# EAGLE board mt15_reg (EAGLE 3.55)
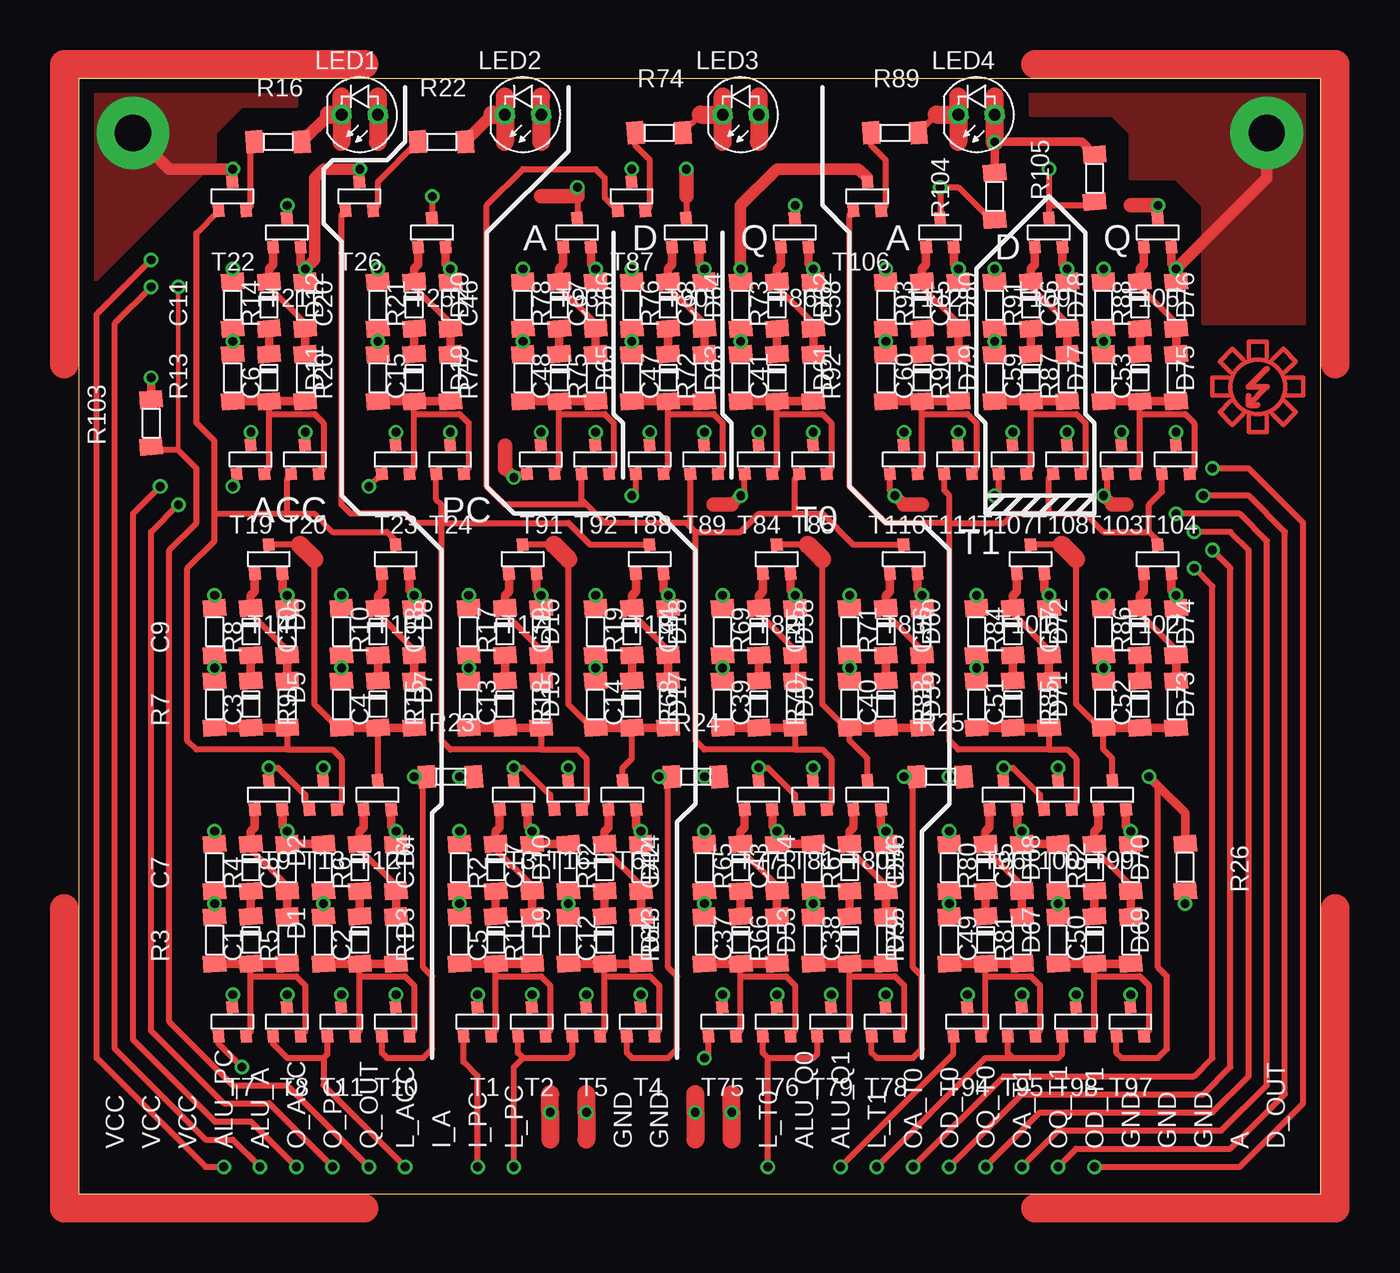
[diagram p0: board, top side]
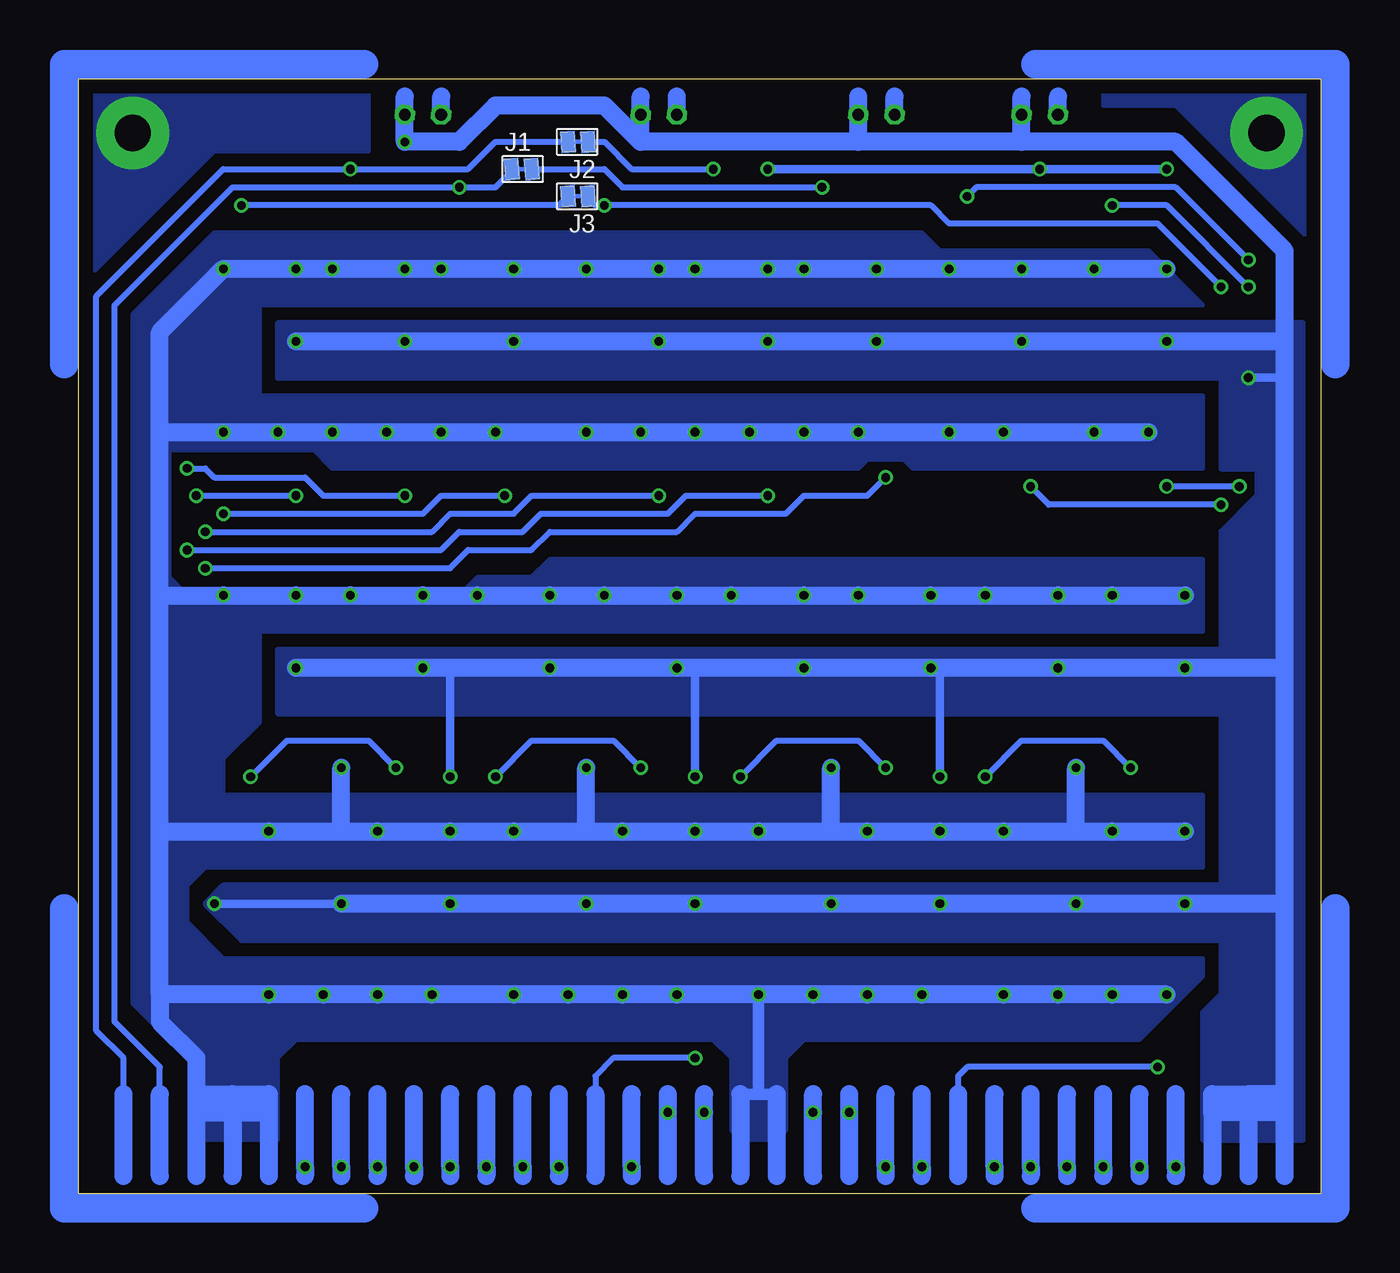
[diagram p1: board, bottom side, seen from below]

Size 86.97 x 78.09 mm. Coordinates in mm from the lower left corner, seen from the top.
Outline: 0,0 86.97,0 86.97,78.09 0,78.09 0,0
Copper layers used: Top, Bottom

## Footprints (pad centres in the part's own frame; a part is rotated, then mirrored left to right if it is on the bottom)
04 = smd 1.194 x 1.6 rotated 4.4:  1.651,0 | smd 1.194 x 1.6 rotated 4.3:  -1.651,0
04D = smd 1.194 x 1.6 rotated 4.3:  1.651,0 | smd 1.194 x 1.6 rotated 4.4:  -1.651,0
MPII = smd 1.016 x 1.524 rotated 4.3:  -0.762,0 | smd 1.016 x 1.524 rotated 4.4:  0.635,0
D-5S = drill 0.813 pad 1.397 octagon:  -1.27,0;  1.27,0
T-23 = smd 0.787 x 0.889 rotated 4.4:  0.991,1.016 | smd 0.787 x 0.889 rotated 4.3:  -0.94,1.016 | smd 0.787 x 0.889 rotated 4.5:  0.025,-1.016

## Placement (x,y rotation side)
C1  1n  [04]  14.61,17.78 90 top
C2  1n  [04]  22.23,17.78 90 top
C3  1n  [04]  14.61,34.29 90 top
C4  1n  [04]  23.5,34.29 90 top
C5  1n  [04]  31.75,17.78 90 top
C6  1n  [04]  15.88,57.15 90 top
C7  100n  [04]  9.53,22.86 90 top
C8  100n  [04]  17.14,22.86 90 top
C9  100n  [04]  9.53,39.37 90 top
C10  100n  [04]  18.41,39.37 90 top
C11  100n  [04]  10.79,62.23 90 top
C12  1n  [04]  39.37,17.78 90 top
C13  1n  [04]  32.38,34.29 90 top
C14  1n  [04]  41.27,34.29 90 top
C15  1n  [04]  26.04,57.15 90 top
C16  100n  [04]  26.67,22.86 90 top
C17  100n  [04]  34.29,22.86 90 top
C18  100n  [04]  27.3,39.37 90 top
C19  100n  [04]  36.2,39.37 90 top
C20  100n  [04]  20.95,62.23 90 top
C37  1n  [04]  48.9,17.78 90 top
C38  1n  [04]  56.52,17.78 90 top
C39  1n  [04]  50.16,34.29 90 top
C40  1n  [04]  59.05,34.29 90 top
C41  1n  [04]  51.44,57.15 90 top
C42  100n  [04]  43.81,22.86 90 top
C43  100n  [04]  51.44,22.86 90 top
C44  100n  [04]  45.09,39.37 90 top
C45  100n  [04]  53.98,39.37 90 top
C46  100n  [04]  31.11,62.23 90 top
C47  1n  [04]  43.81,57.15 90 top
C48  1n  [04]  36.2,57.15 90 top
C49  1n  [04]  66.04,17.78 90 top
C50  1n  [04]  73.66,17.78 90 top
C51  1n  [04]  67.94,34.29 90 top
C52  1n  [04]  76.83,34.29 90 top
C53  1n  [04]  76.83,57.15 90 top
C54  100n  [04]  60.96,22.86 90 top
C55  100n  [04]  68.58,22.86 90 top
C56  100n  [04]  62.87,39.37 90 top
C57  100n  [04]  71.75,39.37 90 top
C58  100n  [04]  56.52,62.23 90 top
C59  1n  [04]  69.22,57.15 90 top
C60  1n  [04]  61.59,57.15 90 top
C65  100n  [04]  64.14,62.23 90 top
C66  100n  [04]  71.75,62.23 90 top
C67  100n  [04]  38.73,62.23 90 top
C68  100n  [04]  46.35,62.23 90 top
D1  1N4148  [04D]  12.06,17.78 270 top
D2  1N4148  [04D]  12.06,22.86 270 top
D3  1N4148  [04D]  19.68,17.78 270 top
D4  1N4148  [04D]  19.68,22.86 270 top
D5  1N4148  [04D]  12.06,34.29 270 top
D6  1N4148  [04D]  12.06,39.37 270 top
D7  1N4148  [04D]  20.95,34.29 270 top
D8  1N4148  [04D]  20.95,39.37 270 top
D9  1N4148  [04D]  29.21,17.78 270 top
D10  1N4148  [04D]  29.21,22.86 270 top
D11  1N4148  [04D]  13.34,57.15 270 top
D12  1N4148  [04D]  13.34,62.23 270 top
D13  1N4148  [04D]  36.83,17.78 270 top
D14  1N4148  [04D]  36.83,22.86 270 top
D15  1N4148  [04D]  29.84,34.29 270 top
D16  1N4148  [04D]  29.84,39.37 270 top
D17  1N4148  [04D]  38.73,34.29 270 top
D18  1N4148  [04D]  38.73,39.37 270 top
D19  1N4148  [04D]  23.5,57.15 270 top
D20  1N4148  [04D]  23.5,62.23 270 top
D53  1N4148  [04D]  46.35,17.78 270 top
D54  1N4148  [04D]  46.35,22.86 270 top
D55  1N4148  [04D]  53.98,17.78 270 top
D56  1N4148  [04D]  53.98,22.86 270 top
D57  1N4148  [04D]  47.62,34.29 270 top
D58  1N4148  [04D]  47.62,39.37 270 top
D59  1N4148  [04D]  56.52,34.29 270 top
D60  1N4148  [04D]  56.52,39.37 270 top
D61  1N4148  [04D]  48.9,57.15 270 top
D62  1N4148  [04D]  48.9,62.23 270 top
D63  1N4148  [04D]  41.27,57.15 270 top
D64  1N4148  [04D]  41.27,62.23 270 top
D65  1N4148  [04D]  33.66,57.15 270 top
D66  1N4148  [04D]  33.66,62.23 270 top
D67  1N4148  [04D]  63.5,17.78 270 top
D68  1N4148  [04D]  63.5,22.86 270 top
D69  1N4148  [04D]  71.12,17.78 270 top
D70  1N4148  [04D]  71.12,22.86 270 top
D71  1N4148  [04D]  65.41,34.29 270 top
D72  1N4148  [04D]  65.41,39.37 270 top
D73  1N4148  [04D]  74.3,34.29 270 top
D74  1N4148  [04D]  74.3,39.37 270 top
D75  1N4148  [04D]  74.3,57.15 270 top
D76  1N4148  [04D]  74.3,62.23 270 top
D77  1N4148  [04D]  66.67,57.15 270 top
D78  1N4148  [04D]  66.67,62.23 270 top
D79  1N4148  [04D]  59.05,57.15 270 top
D80  1N4148  [04D]  59.05,62.23 270 top
J1  JUMPII  [MPII]  55.88,71.75 0 bottom
J2  JUMPII  [MPII]  52.07,73.66 180 bottom
J3  JUMPII  [MPII]  52.07,69.85 180 bottom
LED1  LED-5S  [D-5S]  19.68,75.56 180 top
LED2  LED-5S  [D-5S]  31.11,75.56 180 top
LED3  LED-5S  [D-5S]  46.35,75.56 180 top
LED4  LED-5S  [D-5S]  62.87,75.56 180 top
R1  390  [04]  26.67,17.78 90 top
R2  820  [04]  31.75,22.86 90 top
R3  390  [04]  9.53,17.78 90 top
R4  820  [04]  14.61,22.86 90 top
R5  390  [04]  17.14,17.78 90 top
R6  820  [04]  22.23,22.86 90 top
R7  390  [04]  9.53,34.29 90 top
R8  820  [04]  14.61,39.37 90 top
R9  390  [04]  18.41,34.29 90 top
R10  820  [04]  23.5,39.37 90 top
R11  390  [04]  34.29,17.78 90 top
R12  820  [04]  39.37,22.86 90 top
R13  390  [04]  10.79,57.15 90 top
R14  820  [04]  15.88,62.23 90 top
R15  390  [04]  27.3,34.29 90 top
R16  27  [04]  13.97,73.66 0 top
R17  820  [04]  32.38,39.37 90 top
R18  390  [04]  36.2,34.29 90 top
R19  820  [04]  41.27,39.37 90 top
R20  390  [04]  20.95,57.15 90 top
R21  820  [04]  26.04,62.23 90 top
R22  27  [04]  25.4,73.66 0 top
R23  330  [04]  26.04,29.21 0 top
R24  330  [04]  43.18,29.21 0 top
R25  330  [04]  60.33,29.21 0 top
R26  330  [04]  77.47,22.86 270 top
R64  390  [04]  43.81,17.78 90 top
R65  820  [04]  48.9,22.86 90 top
R66  390  [04]  51.44,17.78 90 top
R67  820  [04]  56.52,22.86 90 top
R68  390  [04]  45.09,34.29 90 top
R69  820  [04]  50.16,39.37 90 top
R70  390  [04]  53.98,34.29 90 top
R71  820  [04]  59.05,39.37 90 top
R72  390  [04]  46.35,57.15 90 top
R73  820  [04]  51.44,62.23 90 top
R74  27  [04]  40.64,74.3 0 top
R75  390  [04]  38.73,57.15 90 top
R76  820  [04]  43.81,62.23 90 top
R77  390  [04]  31.11,57.15 90 top
R78  820  [04]  36.2,62.23 90 top
R79  390  [04]  60.96,17.78 90 top
R80  820  [04]  66.04,22.86 90 top
R81  390  [04]  68.58,17.78 90 top
R82  820  [04]  73.66,22.86 90 top
R83  390  [04]  62.87,34.29 90 top
R84  820  [04]  67.94,39.37 90 top
R85  390  [04]  71.75,34.29 90 top
R86  820  [04]  76.83,39.37 90 top
R87  390  [04]  71.75,57.15 90 top
R88  820  [04]  76.83,62.23 90 top
R89  27  [04]  57.15,74.3 0 top
R90  390  [04]  64.14,57.15 90 top
R91  820  [04]  69.22,62.23 90 top
R92  390  [04]  56.52,57.15 90 top
R93  820  [04]  61.59,62.23 90 top
R103  330  [04]  5.08,53.98 90 top
R104  330  [04]  64.14,69.85 90 top
R105  330  [04]  71.12,71.12 90 top
T1  BC857  [T-23]  27.94,12.06 180 top
T2  BC857  [T-23]  31.75,12.06 180 top
T3  BC847  [T-23]  30.48,27.94 180 top
T4  BC857  [T-23]  39.37,12.06 180 top
T5  BC857  [T-23]  35.56,12.06 180 top
T6  BC847  [T-23]  38.1,27.94 180 top
T7  BC857  [T-23]  10.79,12.06 180 top
T8  BC857  [T-23]  14.61,12.06 180 top
T9  BC847  [T-23]  13.34,27.94 180 top
T10  BC857  [T-23]  22.23,12.06 180 top
T11  BC857  [T-23]  18.41,12.06 180 top
T12  BC847  [T-23]  20.95,27.94 180 top
T13  BC857  [T-23]  17.14,27.94 180 top
T14  BC847  [T-23]  13.34,44.45 180 top
T15  BC847  [T-23]  22.23,44.45 180 top
T16  BC857  [T-23]  34.29,27.94 180 top
T17  BC847  [T-23]  31.11,44.45 180 top
T18  BC847  [T-23]  40.01,44.45 180 top
T19  BC857  [T-23]  12.06,51.44 180 top
T20  BC857  [T-23]  15.88,51.44 180 top
T21  BC847  [T-23]  14.61,67.31 180 top
T22  BC857  [T-23]  10.79,69.85 180 top
T23  BC857  [T-23]  22.23,51.44 180 top
T24  BC857  [T-23]  26.04,51.44 180 top
T25  BC847  [T-23]  24.77,67.31 180 top
T26  BC857  [T-23]  19.68,69.85 180 top
T75  BC857  [T-23]  45.09,12.06 180 top
T76  BC857  [T-23]  48.9,12.06 180 top
T77  BC847  [T-23]  47.62,27.94 180 top
T78  BC857  [T-23]  56.52,12.06 180 top
T79  BC857  [T-23]  52.7,12.06 180 top
T80  BC847  [T-23]  55.24,27.94 180 top
T81  BC857  [T-23]  51.44,27.94 180 top
T82  BC847  [T-23]  48.9,44.45 180 top
T83  BC847  [T-23]  57.78,44.45 180 top
T84  BC857  [T-23]  47.62,51.44 180 top
T85  BC857  [T-23]  51.44,51.44 180 top
T86  BC847  [T-23]  50.16,67.31 180 top
T87  BC857  [T-23]  38.73,69.85 180 top
T88  BC857  [T-23]  40.01,51.44 180 top
T89  BC857  [T-23]  43.81,51.44 180 top
T90  BC847  [T-23]  42.55,67.31 180 top
T91  BC857  [T-23]  32.38,51.44 180 top
T92  BC857  [T-23]  36.2,51.44 180 top
T93  BC847  [T-23]  34.92,67.31 180 top
T94  BC857  [T-23]  62.23,12.06 180 top
T95  BC857  [T-23]  66.04,12.06 180 top
T96  BC847  [T-23]  64.77,27.94 180 top
T97  BC857  [T-23]  73.66,12.06 180 top
T98  BC857  [T-23]  69.85,12.06 180 top
T99  BC847  [T-23]  72.39,27.94 180 top
T100  BC857  [T-23]  68.58,27.94 180 top
T101  BC847  [T-23]  66.67,44.45 180 top
T102  BC847  [T-23]  75.56,44.45 180 top
T103  BC857  [T-23]  73.03,51.44 180 top
T104  BC857  [T-23]  76.83,51.44 180 top
T105  BC847  [T-23]  75.56,67.31 180 top
T106  BC857  [T-23]  55.24,69.85 180 top
T107  BC857  [T-23]  65.41,51.44 180 top
T108  BC857  [T-23]  69.22,51.44 180 top
T109  BC847  [T-23]  67.94,67.31 180 top
T110  BC857  [T-23]  57.78,51.44 180 top
T111  BC857  [T-23]  61.59,51.44 180 top
T112  BC847  [T-23]  60.33,67.31 180 top
U$46  []  82.55,56.52 0 top

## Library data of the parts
C1-C20 C37-C60 C65-C68 D1-D20 D53-D80 R1-R26 R64-R93 R103-R105 = DISCRETE
J1-J3 = jg
LED1-LED4 = M68XXX
T1 T2 T4 T5 T7 T8 T10 T11 T13 T16 T19 T20 T22-T24 T26 T75 T76 T78 T79 T81 T84 T85 T87-T89 T91 T92 T94 T95 T97 T98 T100 T103 T104 T106-T108 T110 T111 = PNP
T3 T6 T9 T12 T14 T15 T17 T18 T21 T25 T77 T80 T82 T83 T86 T90 T93 T96 T99 T101 T102 T105 T109 T112 = NPN
U$46 = TAF

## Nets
A: J1. R104. T93. T112.
ALU_A: T21.
ALU_PC: T25.
ALU_Q0: T75.
ALU_Q1: T94.
D_OUT: J2. R105. T90. T109.
GND: C7. C8. C9. C10. C11. C16. C17. C18. C19. C20. C42. C43. C44. C45. C46. C54. C55. C56. C57. C58. C65. C66. C67. C68. R2. R4. R6. R8. R10. R12. R14. R17. R19. R21. R65. R67. R69. R71. R73. R76. R78. R80. R82. R84. R86. R88. R91. R93. T1. T2. T3. T4. T5. T6. T7. T8. T9. T10. T11. T12. T13. T14. T15. T16. T17. T18. T19. T20. T21. T22. T23. T24. T25. T26. T75. T76. T77. T78. T79. T80. T81. T82. T83. T84. T85. T86. T87. T88. T89. T90. T91. T92. T93. T94. T95. T96. T97. T98. T99. T100. T101. T102. T103. T104. T105. T106. T107. T108. T109. T110. T111. T112.
I_A: T7.
I_PC: T1.
L_ACC: T8. T11.
L_PC: T2. T5.
L_T0: T76. T79.
L_T1: T95. T98.
N$9: C5. D9. R1. T1. T2.
N$10: D9. D10.
N$11: C1. D1. R3. T7. T8.
N$12: D1. D2.
N$13: C5. D10. R2. T3.
N$14: C1. D2. R4. T9.
N$15: D5. D6.
N$17: C2. D3. R5. T10. T11.
N$18: D3. D4.
N$19: C2. D4. R6. T12.
N$20: C3. D6. R8. T14.
N$21: D7. D8.
N$22: C4. D8. R10. T15.
N$23: C4. D7. R9. T12. T14.
N$24: C3. D5. R7. T13. T15. T20. T22.
N$25: R16. T22.
N$26: R24. T3. T4. T16.
N$27: C12. D13. R11. T4. T5.
N$28: D13. D14.
N$29: LED1. R16.
N$30: C6. D11. R13. T19. T20.
N$31: D11. D12.
N$32: C6. D12. R14. T21.
N$33: C12. D14. R12. T6.
N$34: D15. D16.
N$35: C13. D16. R17. T17.
N$36: D17. D18.
N$37: C14. D18. R19. T18.
N$38: C14. D17. R18. T6. T17.
N$39: C13. D15. R15. T16. T18. T24. T26.
N$40: C15. D19. R20. T23. T24.
N$41: D19. D20.
N$42: C15. D20. R21. T25.
N$43: R22. T26.
N$44: LED2. R22.
N$45: R23. T9. T10. T13.
N$93: C37. D53. R64. T75. T76.
N$94: D53. D54.
N$95: C37. D54. R65. T77.
N$96: R25. T77. T78. T81.
N$97: C38. D55. R66. T78. T79.
N$98: D55. D56.
N$99: C38. D56. R67. T80.
N$100: D57. D58.
N$101: C39. D58. R69. T82.
N$102: D59. D60.
N$103: C40. D60. R71. T83.
N$104: C40. D59. R70. T80. T82.
N$105: C39. D57. R68. T81. T83. T85. T87. T89. T92.
N$106: C41. D61. R72. T84. T85.
N$107: D61. D62.
N$108: C41. D62. R73. T86.
N$109: R74. T87.
N$110: LED3. R74.
N$111: C49. D67. R79. T94. T95.
N$112: C47. D63. R75. T88. T89.
N$113: D63. D64.
N$114: C47. D64. R76. T90.
N$115: D67. D68.
N$116: C48. D65. R77. T91. T92.
N$117: D65. D66.
N$118: C48. D66. R78. T93.
N$119: C49. D68. R80. T96.
N$120: R26. T96. T97. T100.
N$121: C50. D69. R81. T97. T98.
N$122: D69. D70.
N$123: C50. D70. R82. T99.
N$124: D71. D72.
N$125: C51. D72. R84. T101.
N$126: D73. D74.
N$127: C52. D74. R86. T102.
N$128: C52. D73. R85. T99. T101.
N$129: C51. D71. R83. T100. T102. T104. T106. T108. T111.
N$130: C53. D75. R87. T103. T104.
N$131: D75. D76.
N$132: C53. D76. R88. T105.
N$133: R89. T106.
N$134: LED4. R89.
N$135: C59. D77. R90. T107. T108.
N$136: D77. D78.
N$137: C59. D78. R91. T109.
N$138: C60. D79. R92. T110. T111.
N$139: D79. D80.
N$140: C60. D80. R93. T112.
O_ACC: T19.
O_PC: T23.
OA_T0: T91.
OA_T1: T110.
OD_T0: T88.
OD_T1: T107.
OQ_T0: T84.
OQ_T1: T103.
Q_OUT: J3. R103. T86. T105.
VCC: C7. C8. C9. C10. C11. C16. C17. C18. C19. C20. C42. C43. C44. C45. C46. C54. C55. C56. C57. C58. C65. C66. C67. C68. LED1. LED2. LED3. LED4. R1. R3. R5. R7. R9. R11. R13. R15. R18. R20. R23. R24. R25. R26. R64. R66. R68. R70. R72. R75. R77. R79. R81. R83. R85. R87. R90. R92. R103. R104. R105.

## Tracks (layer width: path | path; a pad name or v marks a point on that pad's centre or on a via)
A  (via drill 0.61 pad 1.02)
  Top 0.406: T93. 34.92,68.35 34.92,69.85 | T112. 60.33,68.35 v60.33,70.48 61.59,70.48 63.88,68.2 R104.
  Top 1.016: v34.92,70.48 34.92,69.85 32.38,69.85
  Bottom 0.305: 56.64,71.75 J1.
  Bottom 0.406: 81.28,6.99 81.28,8.89 84.45,12.06 84.45,62.23 76.2,70.48 v60.33,70.48 57.78,70.48 56.64,71.63 56.64,71.75 | J1. 50.16,71.75 48.9,70.48 v34.92,70.48
  Bottom 1.27: 81.28,1.27 81.28,6.99
ALU_A  (via drill 0.61 pad 1.02)
  Top 0.406: T21. 14.61,68.35 v14.61,69.22 | v5.08,63.5 2.54,60.96 2.54,10.16 8.89,3.81 10.79,3.81 v12.7,1.91
  Bottom 0.406: v14.61,69.22 10.79,69.22 v5.08,63.5
  Bottom 1.27: 12.7,1.27 v12.7,1.91 12.7,6.99
ALU_PC  (via drill 0.61 pad 1.02)
  Top 0.406: T25. 24.77,68.35 v24.77,69.85 | v5.08,65.41 1.27,61.59 1.27,9.53 8.89,1.91 v10.16,1.91
  Bottom 0.406: v5.08,65.41 10.16,70.48 24.13,70.48 v24.77,69.85
  Bottom 1.27: 10.16,1.27 v10.16,1.91 10.16,6.99
ALU_Q0  (via drill 0.61 pad 1.02)
  Top 0.406: 44.09,11.05 44.09,9.8 v43.81,9.53
  Bottom 0.406: 50.8,6.99 50.8,8.26 49.53,9.53 v43.81,9.53
  Bottom 1.27: 50.8,6.99 50.8,1.27
ALU_Q1  (via drill 0.61 pad 1.02)
  Top 0.406: 61.24,11.05 61.24,9.8 v53.34,1.91
  Bottom 1.27: 53.34,1.27 v53.34,1.91 53.34,6.99
D_OUT  (via drill 0.61 pad 1.02)
  Top 0.406: T90. 42.55,68.35 42.55,69.85 | T109. 67.94,68.35 67.94,69.22 | v67.94,71.75 67.94,69.22 | R105. 70.87,69.22 67.94,69.22
  Top 1.016: v42.55,71.75 42.55,69.85
  Bottom 0.305: J2. 51.31,73.66
  Bottom 0.406: 83.82,6.99 83.82,9.53 85.72,11.43 85.72,62.87 76.83,71.75 v67.94,71.75 59.69,71.75 57.78,73.66 J2. | 51.31,73.66 50.16,73.66 48.26,71.75 v42.55,71.75
  Bottom 1.27: 83.82,1.27 83.82,6.99
GND  (via drill 0.61 pad 1.02, 2.54 pad 5.08)
  Top 0.406: T22. 10.79,70.89 v10.79,71.75 | T26. 19.68,70.89 v19.68,71.75 | T87. 38.73,70.89 v38.73,71.75
  Top 0.61: T7. 10.79,13.11 v10.79,13.97 | T8. 14.61,13.11 v14.61,13.97 | T1. 27.94,13.11 v27.94,13.97 | T2. 31.75,13.11 v31.75,13.97 | T75. 45.09,13.11 v45.09,13.97 | T76. 48.9,13.11 v48.9,13.97 | T94. 62.23,13.11 v62.23,13.97 | T95. 66.04,13.11 v66.04,13.97 | 14.28,26.92 14.28,25.73 v14.61,25.4 14.61,24.51 17.14,24.51 | v9.53,25.4 9.53,24.51 | 21.89,26.92 21.89,25.73 v22.23,25.4 22.23,24.51 | 34.29,24.51 31.75,24.51 v31.75,25.4 31.42,25.73 31.42,26.92 | 51.44,24.51 48.9,24.51 v48.9,25.4 48.56,25.73 48.56,26.92 | 68.58,24.51 66.04,24.51 v66.04,25.4 65.71,25.73 65.71,26.92 | 73.33,26.92 73.33,25.73 v73.66,25.4 73.66,24.51 | 56.19,26.92 56.19,25.73 v56.52,25.4 56.52,24.51 | v43.81,25.4 43.81,24.51 | 39.04,26.92 39.04,25.73 v39.37,25.4 39.37,24.51 | v26.67,25.4 26.67,24.51 | v60.96,25.4 60.96,24.51 | T13. 17.14,28.98 v17.14,29.84 | T16. 34.29,28.98 v34.29,29.84 | T81. 51.44,28.98 v51.44,29.84 | T100. 68.58,28.98 v68.58,29.84 | 14.28,43.43 14.28,42.24 v14.61,41.91 14.61,41.02 | 23.16,43.43 23.16,42.24 v23.5,41.91 23.5,41.02 | 32.05,43.43 32.05,42.24 v32.38,41.91 32.38,41.02 | 40.95,43.43 40.95,42.24 v41.27,41.91 41.27,41.02 | 49.84,43.43 49.84,42.24 v50.16,41.91 50.16,41.02 | 58.73,43.43 58.73,42.24 v59.05,41.91 59.05,41.02 | 67.61,43.43 67.61,42.24 v67.94,41.91 67.94,41.02 | 76.5,43.43 76.5,42.24 v76.83,41.91 76.83,41.02 | v9.53,41.91 9.53,41.02 | v18.41,41.91 18.41,41.02 | v27.3,41.91 27.3,41.02 | v36.2,41.91 36.2,41.02 | v45.09,41.91 45.09,41.02 | v53.98,41.91 53.98,41.02 | v62.87,41.91 62.87,41.02 | v71.75,41.91 71.75,41.02 | 68.89,66.29 68.89,65.1 v69.22,64.77 69.22,63.88 | 76.5,66.29 76.5,65.1 v76.83,64.77 76.83,63.88
  Top 0.61: 61.27,66.29 61.27,65.1 v61.59,64.77 61.59,63.88 | v64.14,64.77 64.14,63.88 | v71.75,64.77 71.75,63.88 | v56.52,64.77 56.52,63.88 | 51.1,66.29 51.1,65.1 v51.44,64.77 51.44,63.88 | 35.87,66.29 35.87,65.1 v36.2,64.77 36.2,63.88 | v38.73,64.77 38.73,63.88 | v31.11,64.77 31.11,63.88 | 43.48,66.29 43.48,65.1 v43.81,64.77 43.81,63.88 | 15.54,66.29 15.54,65.1 v15.88,64.77 15.88,63.88 | 25.7,66.29 25.7,65.1 v26.04,64.77 26.04,63.88 26.04,63.5 | v20.95,64.77 20.95,63.88 | v10.79,64.77 10.79,63.88 | v46.35,64.77 46.35,63.88 | T19. 12.06,52.48 v12.06,53.34 | T20. 15.88,52.48 v15.88,53.34 | T23. 22.23,52.48 v22.23,53.34 | T24. 26.04,52.48 v26.04,53.34 | T91. 32.38,52.48 v32.38,53.34 | T92. 36.2,52.48 v36.2,53.34 | T88. 40.01,52.48 v40.01,53.34 | T89. 43.81,52.48 v43.81,53.34 | T84. 47.62,52.48 v47.62,53.34 | T85. 51.44,52.48 v51.44,53.34 | T110. 57.78,52.48 v57.78,53.34 | T111. 61.59,52.48 v61.59,53.34 | T104. 76.83,52.48 v76.83,53.34 | T103. 73.03,52.48 v73.03,53.34 | T108. 69.22,52.48 v69.22,53.34 | T107. 65.41,52.48 v65.41,53.34 | T98. 69.85,13.11 v69.85,13.97 | T97. 73.66,13.11 v73.66,13.97 | T11. 18.41,13.11 v18.41,13.97 | T10. 22.23,13.11 v22.23,13.97 | T5. 35.56,13.11 v35.56,13.97 | T4. 39.37,13.11 v39.37,13.97 | T79. 52.7,13.11 v52.7,13.97 | T78. 56.52,13.11 v56.52,13.97
  Top 0.813: v46.35,64.77 46.35,69.22 48.9,71.75 54.61,71.75 55.22,71.14 T106. | v15.88,64.77 16.51,65.41 16.51,71.12 17.14,71.75 v19.68,71.75 | v76.83,64.77 83.19,71.12 v83.19,74.3 | v10.79,71.75 6.35,71.75 v3.81,74.3
  Bottom 0.61: v10.79,71.75 v19.68,71.75 v38.73,71.75
  Bottom 0.813: 39.37,6.99 38.1,6.99 | 39.37,6.99 40.64,6.99 | v39.37,13.97 39.37,6.99
  Bottom 1.27: v10.79,13.97 v14.61,13.97 v18.41,13.97 v22.23,13.97 v27.94,13.97 v31.75,13.97 v35.56,13.97 v39.37,13.97 v45.09,13.97 v48.9,13.97 v52.7,13.97 v56.52,13.97 v62.23,13.97 v66.04,13.97 v69.85,13.97 v73.66,13.97 81.28,13.97 | 68.58,25.4 v66.04,25.4 v60.96,25.4 v56.52,25.4 51.44,25.4 | 68.58,25.4 v73.66,25.4 81.28,25.4 | 51.44,25.4 v48.9,25.4 v43.81,25.4 v39.37,25.4 34.29,25.4 | 34.29,25.4 v31.75,25.4 v26.67,25.4 v22.23,25.4 17.14,25.4 | 17.14,25.4 v14.61,25.4 v9.53,25.4 | 17.14,25.4 v17.14,29.84 | 34.29,25.4 v34.29,29.84 | 51.44,25.4 v51.44,29.84 | 68.58,25.4 v68.58,29.84 | v9.53,41.91 v14.61,41.91 v18.41,41.91 v23.5,41.91 v27.3,41.91 v32.38,41.91 v36.2,41.91 v41.27,41.91 v45.09,41.91 v50.16,41.91 v53.98,41.91 v59.05,41.91 v62.87,41.91 v67.94,41.91 v71.75,41.91 v76.83,41.91 81.28,41.91 | v10.79,64.77 v15.88,64.77 v20.95,64.77 v26.04,64.77 v31.11,64.77 v36.2,64.77 v38.73,64.77 v43.81,64.77 v46.35,64.77 v51.44,64.77 v56.52,64.77 v61.59,64.77 v64.14,64.77 v69.22,64.77 v71.75,64.77 v76.83,64.77 81.28,60.33 81.28,53.34 | 81.28,13.97 81.28,25.4 | 81.28,25.4 81.28,41.91 | 81.28,41.91 81.28,53.34 | v12.06,53.34 v15.88,53.34 v22.23,53.34 v26.04,53.34 v32.38,53.34 v36.2,53.34 v40.01,53.34 v43.81,53.34 v47.62,53.34 v51.44,53.34 v57.78,53.34 v61.59,53.34 v65.41,53.34 v69.22,53.34 v73.03,53.34 v76.83,53.34 81.28,53.34 | 81.28,13.97 81.28,12.06 78.74,9.53 78.74,6.99 | 78.74,6.99 78.74,5.71 | 78.74,5.71 78.74,1.27 | 76.2,6.99 76.2,1.27 | 78.74,6.99 76.2,6.99 | 73.66,5.71 73.66,6.99 76.2,6.99 | 73.66,5.71 73.66,1.27 | 38.1,6.99 38.1,1.27 | 40.64,6.99 40.64,1.27 | 78.74,5.71 73.66,5.71
  pour Bottom (isolate 0.356): 73.03,3.81 73.03,9.53 71.75,10.79 42.55,10.79 41.27,9.53 41.27,4.45 40.64,3.81 38.1,3.81 37.47,4.45 37.47,9.53 36.2,10.79 12.7,10.79 8.26,15.24 8.26,16.51 76.83,16.51 79.38,19.05 79.38,21.59 78.11,22.86 8.26,22.86 8.26,27.94 76.83,27.94 76.83,30.48 74.3,33.02 74.3,39.37 8.26,39.37 8.26,44.45 53.98,44.45 55.24,43.18 59.05,43.18 60.33,41.91 79.38,41.91 80.64,43.18 80.64,52.07 70.48,52.07 69.22,50.8 32.38,50.8 31.75,51.44 29.21,51.44 28.57,50.8 8.26,50.8 8.26,55.88 74.3,55.88 74.3,62.23 8.26,62.23 12.06,66.04 26.67,66.04 27.94,67.31 77.47,67.31 83.19,61.59 83.19,13.34 78.74,8.89 78.74,3.81
  pour Top (isolate 0.356): 0.64,63.5 0.64,77.47 15.24,77.47 15.24,76.2 11.43,76.2 9.53,74.3 9.53,72.39
  pour Bottom (isolate 0.356): 0.64,77.47 0.64,66.67 10.16,76.2 15.24,76.2 15.24,77.47
  pour Bottom (isolate 0.356): 86.36,77.47 86.36,64.14 77.47,73.03 66.67,73.03 66.67,77.47
  pour Top (isolate 0.356): 86.36,77.47 66.67,77.47 66.67,75.56 72.39,75.56 73.66,74.3 73.66,71.12 76.83,71.12 78.74,69.22 78.74,60.96 86.36,60.96
I_A  (via drill 0.61 pad 1.02)
  Top 0.406: 9.8,11.05 9.8,10.52 v11.43,8.89
  Bottom 0.406: 25.4,6.99 25.4,8.26 24.77,8.89 v11.43,8.89
  Bottom 1.27: 25.4,6.99 25.4,1.27
I_PC  (via drill 0.61 pad 1.02)
  Top 0.406: v27.94,1.91 27.94,8.26 26.95,9.25 26.95,11.05
  Bottom 1.27: 27.94,6.99 v27.94,1.91 27.94,1.27
L_ACC  (via drill 0.61 pad 1.02)
  Top 0.406: 13.61,11.05 13.61,10.52 14.61,9.53 17.14,9.53 | 17.42,11.05 17.42,9.8 17.14,9.53 | 17.14,9.53 17.14,7.62 v22.86,1.91
  Bottom 1.27: 22.86,1.27 v22.86,1.91 22.86,6.99
L_PC  (via drill 0.61 pad 1.02)
  Top 0.406: 30.76,11.05 30.76,9.88 31.11,9.53 | 34.57,11.05 34.57,9.8 34.29,9.53 31.11,9.53 | v30.48,1.91 30.48,8.89 31.11,9.53 | 31.11,9.53 31.75,9.53
  Bottom 1.27: 30.48,1.27 v30.48,1.91 30.48,6.99
L_T0  (via drill 0.61 pad 1.02)
  Top 0.406: 47.9,11.05 47.9,9.88 48.26,9.53 | 51.71,11.05 51.71,9.8 51.44,9.53 48.26,9.53 | v48.26,1.91 48.26,9.53
  Bottom 1.27: 48.26,1.27 v48.26,1.91 48.26,6.99
L_T1  (via drill 0.61 pad 1.02)
  Top 0.406: 65.05,11.05 65.05,9.88 65.41,9.53 | 68.86,11.05 68.86,9.8 68.58,9.53 65.41,9.53 | 65.41,9.53 63.5,9.53 v55.88,1.91
  Bottom 1.27: 55.88,1.27 v55.88,1.91 55.88,6.99
N$1
  Top 2: 20,-1 -1,-1 -1,20
N$2
  Top 2: 66.97,-1 87.97,-1 87.97,20
N$3
  Top 2: 20,79.09 -1,79.09 -1,58.09
N$4
  Top 2: 87.97,58.09 87.97,79.09 66.97,79.09
N$5
  Bottom 2: 20,-1 -1,-1 -1,20
N$6
  Bottom 2: 66.97,-1 87.97,-1 87.97,20
N$7
  Bottom 2: 20,79.09 -1,79.09 -1,58.09
N$8
  Bottom 2: 87.97,58.09 87.97,79.09 66.97,79.09
N$9
  Top 0.406: 28.88,11.05 28.88,11.1 29.21,11.43 29.21,15.24 | 29.21,15.24 29.21,16.13 | 32.69,11.05 32.69,11.1 33.02,11.43 33.02,14.61 32.38,15.24 29.21,15.24
  Top 0.61: R1. 29.21,16.13 C5.
N$10
  Top 0.61: D9. 29.21,21.21
N$11
  Top 0.406: 11.73,11.05 12.06,11.38 12.06,15.24 | 15.54,11.05 15.88,11.38 15.88,14.61 15.24,15.24 12.06,15.24 | 12.06,15.24 12.06,16.13
  Top 0.61: R3. 12.06,16.13 C1.
N$12
  Top 0.61: D1. 12.06,21.21
N$13
  Top 0.406: R2. 31.75,21.59 29.21,24.13 D10.
  Top 0.61: 31.75,19.43 R2. | 29.49,26.92 29.49,25.68 29.21,25.4 D10.
N$14
  Top 0.406: R4. 14.61,21.59 12.06,24.13 D2.
  Top 0.61: 14.61,19.43 R4. | 12.34,26.92 12.34,25.68 12.06,25.4 D2.
N$15
  Top 0.61: 12.06,37.72 D5.
N$17
  Top 0.406: 19.68,15.24 19.68,11.43 19.36,11.1 19.36,11.05 | 19.68,15.24 19.68,16.13 | 19.68,15.24 22.86,15.24 23.5,14.61 23.5,11.43 23.16,11.1 23.16,11.05
  Top 0.61: R5. 19.68,16.13 C2.
N$18
  Top 0.61: D3. 19.68,21.21
N$19
  Top 0.406: R6. 22.23,21.59 19.68,24.13 D4.
  Top 0.61: 22.23,19.43 R6. | 19.96,26.92 19.96,25.68 19.68,25.4 D4.
N$20
  Top 0.406: R8. 14.61,38.1 12.06,40.64 D6.
  Top 0.61: R8. 14.61,35.94 | 12.34,43.43 12.34,42.19 12.06,41.91 D6.
N$21
  Top 0.61: 20.95,37.72 D7.
N$22
  Top 0.406: R10. 23.5,38.1 20.95,40.64 D8.
  Top 0.61: R10. 23.5,35.94 | 21.23,43.43 21.23,42.19 20.95,41.91 D8.
N$23
  Top 0.406: R9. 18.16,32.64 16.51,34.29 16.51,44.45 | 15.49,45.47 T14. | T12. 20.95,28.96 20.95,32.64
  Top 0.61: C4. 20.95,32.64 R9.
  Top 1.27: 16.51,44.45 15.49,45.47
N$24
  Top 0.406: 18.09,26.92 18.09,26.98 18.41,27.3 18.41,30.48 17.78,31.11 14.61,31.11 | C3. 14.61,31.11 | 14.61,31.11 8.26,31.11 7.62,31.75 7.62,43.81 9.53,45.72 9.53,47.62 | 14.88,50.42 14.61,50.14 14.61,47.62 | 9.53,47.62 14.61,47.62 | T15. 22.2,45.74 21.59,46.35 17.78,46.35 16.51,47.62 14.61,47.62 | 9.8,68.83 8.26,67.28 8.26,53.98 9.53,52.7 9.53,47.62
  Top 0.61: C3. 12.06,32.64 R7.
N$25
  Top 0.406: 11.73,68.83 12.06,69.16 12.06,73.41 R16.
N$26  (via drill 0.61 pad 1.02)
  Top 0.406: T3. 30.45,29.82 v30.48,29.84 31.11,29.84 33.02,27.94 33.02,27.3 33.3,27.03 33.3,26.92 | 38.38,11.05 38.38,9.88 38.73,9.53 41.27,9.53 41.91,10.16 41.91,15.24 41.27,15.88 41.27,28.57 v40.64,29.21
  Top 0.61: v40.64,29.21 R24.
  Bottom 0.406: v30.48,29.84 32.38,31.75 38.1,31.75 v40.64,29.21
N$27
  Top 0.406: 36.83,15.24 36.83,11.43 36.5,11.1 36.5,11.05 | 36.83,15.24 36.83,16.13 | 36.83,15.24 40.01,15.24 40.64,14.61 40.64,11.43 40.31,11.1 40.31,11.05
  Top 0.61: R11. 36.83,16.13 C12.
N$28
  Top 0.61: D13. 36.83,21.21
N$29
  Top 0.813: 15.62,73.66 17.53,75.56
  Top 1.27: 17.53,75.56 LED1. | LED1. 18.41,76.83 | LED1. 18.41,73.66
  Bottom 1.27: LED1. 18.41,76.83
N$30
  Top 0.406: 13.01,50.42 13.01,50.47 13.34,50.8 13.34,54.61 | 13.34,54.61 13.34,55.5 | 16.82,50.42 16.82,50.47 17.14,50.8 17.14,53.98 16.51,54.61 13.34,54.61
  Top 0.61: R13. 13.34,55.5 C6.
N$31
  Top 0.61: 13.34,60.58 D11.
N$32
  Top 0.406: R14. 15.88,60.96 13.34,63.5 D12.
  Top 0.61: R14. 15.88,58.8 | 13.61,66.29 13.61,65.05 13.34,64.77 D12.
N$33
  Top 0.406: R12. 39.37,21.59 36.83,24.13 D14.
  Top 0.61: 39.37,19.43 R12. | 37.11,26.92 37.11,25.68 36.83,25.4 D14.
N$34
  Top 0.61: 29.84,37.72 D15.
N$35
  Top 0.406: R17. 32.38,38.1 29.84,40.64 D16.
  Top 0.61: R17. 32.38,35.94 | D16. 29.84,41.91 30.12,42.19 30.12,43.43
N$36
  Top 0.61: 38.73,37.72 D17.
N$37
  Top 0.406: R19. 41.27,38.1 38.73,40.64 D18.
  Top 0.61: R19. 41.27,35.94 | 39.01,43.43 39.01,42.19 38.73,41.91 D18.
N$38
  Top 0.406: R18. 35.94,32.64 34.29,34.29 34.29,44.45 | 33.27,45.47 T17. | T6. 38.08,29.82 38.73,30.48 38.73,32.64
  Top 0.61: C14. 38.73,32.64 R18.
  Top 1.27: 34.29,44.45 33.27,45.47
N$39
  Top 0.406: C13. 32.38,31.11 | 32.38,31.11 34.92,31.11 35.56,30.48 35.56,27.3 35.23,26.98 35.23,26.92 | 32.38,31.11 26.04,31.11 25.4,31.75 25.4,46.99 | 25.04,50.42 25.04,48.62 25.4,48.26 25.4,46.99 | T18. 35.81,45.47 34.29,46.99 25.4,46.99 | 25.4,46.99 23.5,46.99 22.86,47.62 19.05,47.62 18.41,48.26 18.41,68.56 18.69,68.83
  Top 0.61: C13. 29.84,32.64 R15.
N$40
  Top 0.406: 23.16,50.42 23.16,50.47 23.5,50.8 23.5,54.61 | 23.5,54.61 23.5,55.5 | 26.98,50.42 26.98,50.47 27.3,50.8 27.3,53.98 26.67,54.61 23.5,54.61
  Top 0.61: R20. 23.5,55.5 C15.
N$41
  Top 0.61: 23.5,60.58 D19.
N$42
  Top 0.406: R21. 26.04,60.96 23.5,63.5 D20.
  Top 0.61: R21. 26.04,58.8 | 23.77,66.29 23.77,65.05 23.5,64.77 D20.
N$43
  Top 0.406: 20.62,68.83 20.95,69.16 20.95,70.87 R22.
N$44
  Top 0.813: 27.05,73.66 28.96,75.56
  Top 1.27: 28.96,75.56 LED2. | LED2. 29.84,76.83 | LED2. 29.84,73.66
  Bottom 1.27: LED2. 29.84,76.83
N$45  (via drill 0.61 pad 1.02)
  Top 0.406: T9. 13.34,28.98 v13.34,29.84 13.97,29.84 15.88,27.94 15.88,27.3 16.15,27.03 16.15,26.92 | 21.23,11.05 21.23,9.88 21.59,9.53 24.13,9.53 24.77,10.16 24.77,15.24 24.13,15.88 24.13,28.57 v23.5,29.21
  Top 0.61: v23.5,29.21 R23.
  Bottom 0.406: v13.34,29.84 15.24,31.75 20.95,31.75 v23.5,29.21
N$47  (via drill 0.61 pad 1.02)
  Top 1.27: 33.02,3.81 v33.02,5.71 33.02,6.99
  Bottom 1.27: 33.02,1.27 v33.02,5.71 33.02,6.99
N$48  (via drill 0.61 pad 1.02)
  Top 1.27: 35.56,6.99 v35.56,5.71 35.56,3.81
  Bottom 1.27: 35.56,1.27 v35.56,5.71 35.56,6.99
N$51  (via drill 0.61 pad 1.02)
  Top 1.27: 45.72,3.81 v45.72,5.71 45.72,6.99
  Bottom 1.27: 45.72,1.27 v45.72,5.71 45.72,6.99
N$53  (via drill 0.61 pad 1.02)
  Top 1.27: 43.18,6.99 v43.18,5.71 43.18,3.81
  Bottom 1.27: 43.18,1.27 v43.18,5.71 43.18,6.99
N$93
  Top 0.406: 46.02,11.05 46.02,11.1 46.35,11.43 46.35,15.24 | 46.35,15.24 46.35,16.13 | 49.84,11.05 49.84,11.1 50.16,11.43 50.16,14.61 49.53,15.24 46.35,15.24
  Top 0.61: R64. 46.35,16.13 C37.
N$94
  Top 0.61: D53. 46.35,21.21
N$95
  Top 0.406: R65. 48.9,21.59 46.35,24.13 D54.
  Top 0.61: 48.9,19.43 R65. | 46.63,26.92 46.63,25.68 46.35,25.4 D54.
N$96  (via drill 0.61 pad 1.02)
  Top 0.406: T77. 47.6,29.82 v47.62,29.84 48.26,29.84 50.16,27.94 50.16,27.3 50.44,27.03 50.44,26.92 | 55.52,11.05 55.52,9.88 55.88,9.53 58.42,9.53 59.05,10.16 59.05,15.24 58.42,15.88 58.42,28.57 v57.78,29.21
  Top 0.61: v57.78,29.21 R25.
  Bottom 0.406: v47.62,29.84 49.53,31.75 55.24,31.75 v57.78,29.21
N$97
  Top 0.406: 53.98,15.24 53.98,11.43 53.65,11.1 53.65,11.05 | 53.98,15.24 53.98,16.13 | 53.98,15.24 57.15,15.24 57.78,14.61 57.78,11.43 57.45,11.1 57.45,11.05
  Top 0.61: C38. 53.98,16.13 R66.
N$98
  Top 0.61: D55. 53.98,21.21
N$99
  Top 0.406: R67. 56.52,21.59 53.98,24.13 D56.
  Top 0.61: 56.52,19.43 R67. | 54.25,26.92 54.25,25.68 53.98,25.4 D56.
N$100
  Top 0.61: 47.62,37.72 D57.
N$101
  Top 0.406: R69. 50.16,38.1 47.62,40.64 D58.
  Top 0.61: R69. 50.16,35.94 | 47.9,43.43 47.9,42.19 47.62,41.91 D58.
N$102
  Top 0.61: 56.52,37.72 D59.
N$103
  Top 0.406: R71. 59.05,38.1 56.52,40.64 D60.
  Top 0.61: R71. 59.05,35.94 | 56.79,43.43 56.79,42.19 56.52,41.91 D60.
N$104
  Top 0.406: 51.05,45.47 T82. | 52.07,44.45 52.07,34.29 53.72,32.64 R70. 53.98,31.75 55.22,30.5 T80.
  Top 0.61: C40. 56.52,32.64 R70.
  Top 1.27: 52.07,44.45 51.05,45.47
N$105
  Top 0.406: 52.38,26.92 52.38,26.98 52.7,27.3 52.7,30.48 52.07,31.11 50.16,31.11 | C39. 50.16,31.11 | 50.16,31.11 43.81,31.11 43.18,31.75 43.18,46.35 | 42.82,50.42 42.82,46.71 43.18,46.35 | T83. 54.23,45.47 52.07,47.62 50.16,47.62 | 43.18,46.35 46.35,46.35 47.62,47.62 50.16,47.62 | 50.44,50.42 50.16,50.14 50.16,47.62 | 35.2,50.42 35.2,48.62 35.56,48.26 | 35.56,48.26 36.83,46.99 42.55,46.99 43.18,46.35 | 35.56,48.26 29.84,48.26 28.57,49.53 28.57,69.22 31.11,71.75 36.2,71.75 36.83,71.12 36.83,69.75 37.74,68.83
  Top 0.61: R68. 47.62,32.64 C39.
N$106
  Top 0.406: 48.56,50.42 48.56,50.47 48.9,50.8 48.9,54.61 | 48.9,54.61 48.9,55.5 | 52.38,50.42 52.38,50.47 52.7,50.8 52.7,53.98 52.07,54.61 48.9,54.61
  Top 0.61: R72. 48.9,55.5 C41.
N$107
  Top 0.61: 48.9,60.58 D61.
N$108
  Top 0.406: R73. 51.44,60.96 48.9,63.5 D62.
  Top 0.61: R73. 51.44,58.8 | 49.17,66.29 49.17,65.05 48.9,64.77 D62.
N$109
  Top 0.406: 39.67,68.83 40.01,69.16 40.01,72.39 38.99,73.41 R74.
N$110
  Top 0.406: 42.29,74.3 43.56,75.56
  Top 1.27: 43.56,75.56 LED3. | LED3. 45.09,76.83 | LED3. 45.09,73.66
  Bottom 1.27: LED3. 45.09,76.83
N$111
  Top 0.406: 63.17,11.05 63.17,11.1 63.5,11.43 63.5,15.24 | 66.98,11.05 66.98,11.1 67.31,11.43 67.31,14.61 66.67,15.24 63.5,15.24 | 63.5,15.24 63.5,16.13
  Top 0.61: C49. 63.5,16.13 R79.
N$112
  Top 0.406: 44.76,50.42 44.76,50.47 45.09,50.8 45.09,53.98 44.45,54.61 41.27,54.61 | 40.95,50.42 40.95,50.47 41.27,50.8 41.27,54.61 | 41.27,54.61 41.27,55.5
  Top 0.61: R75. 41.27,55.5 C47.
N$113
  Top 0.61: 41.27,60.58 D63.
N$114
  Top 0.406: R76. 43.81,60.96 41.27,63.5 D64.
  Top 0.61: R76. 43.81,58.8 | 41.55,66.29 41.55,65.05 41.27,64.77 D64.
N$115
  Top 0.61: D67. 63.5,21.21
N$116
  Top 0.406: 33.33,50.42 33.33,50.47 33.66,50.8 33.66,54.61 | 33.66,54.61 33.66,55.5 | 37.13,50.42 37.13,50.47 37.47,50.8 37.47,53.98 36.83,54.61 33.66,54.61
  Top 0.61: R77. 33.66,55.5 C48.
N$117
  Top 0.61: 33.66,60.58 D65.
N$118
  Top 0.406: R78. 36.2,60.96 33.66,63.5 D66.
  Top 0.61: R78. 36.2,58.8 | 33.93,66.29 33.93,65.05 33.66,64.77 D66.
N$119
  Top 0.406: R80. 66.04,21.59 63.5,24.13 D68.
  Top 0.61: 66.04,19.43 R80. | 63.78,26.92 63.78,25.68 63.5,25.4 D68.
N$120  (via drill 0.61 pad 1.02)
  Top 0.406: 67.59,26.92 67.59,27.03 67.31,27.3 67.31,27.94 65.41,29.84 v64.77,29.84 64.75,29.82 T96. | 72.67,11.05 72.67,9.88 73.03,9.53 75.56,9.53 76.2,10.16 76.2,15.24 75.56,15.88 75.56,28.57
  Top 0.61: v74.93,29.21 75.56,28.57 77.47,26.67 R26.
  Bottom 0.406: v64.77,29.84 66.67,31.75 72.39,31.75 v74.93,29.21
N$121
  Top 0.406: 71.12,15.24 71.12,11.43 70.79,11.1 70.79,11.05 | 71.12,15.24 71.12,16.13 | 71.12,15.24 74.3,15.24 74.93,14.61 74.93,11.43 74.6,11.1 74.6,11.05
  Top 0.61: C50. 71.12,16.13 R81.
N$122
  Top 0.61: D69. 71.12,21.21
N$123
  Top 0.406: R82. 73.66,21.59 71.12,24.13 D70.
  Top 0.61: 73.66,19.43 R82. | 71.4,26.92 71.4,25.68 71.12,25.4 D70.
N$124
  Top 0.61: 65.41,37.72 D71.
N$125
  Top 0.406: R84. 67.94,38.1 65.41,40.64 D72.
  Top 0.61: R84. 67.94,35.94 | 65.68,43.43 65.68,42.19 65.41,41.91 D72.
N$126
  Top 0.61: 74.3,37.72 D73.
N$127
  Top 0.406: R86. 76.83,38.1 74.3,40.64 D74.
  Top 0.61: R86. 76.83,35.94 | 74.57,43.43 74.57,42.19 74.3,41.91 D74.
N$128
  Top 0.406: 68.83,45.47 T101. | 69.85,44.45 69.85,34.29 71.5,32.64 R85. 71.75,31.11 72.36,30.5 T99.
  Top 0.61: R85. 74.3,32.64 C52.
  Top 1.27: 69.85,44.45 68.83,45.47
N$129
  Top 0.406: 67.94,31.11 69.22,31.11 69.85,30.48 69.85,27.3 69.52,26.98 69.52,26.92 | C51. 67.94,31.11 | 67.94,31.11 61.59,31.11 60.96,31.75 60.96,46.99 | 60.6,50.42 60.6,49.25 60.96,48.9 60.96,46.99 | T102. 75.54,45.74 74.93,46.35 | 75.84,50.42 75.84,49.17 74.93,48.26 74.93,46.35 | 60.96,46.99 64.77,46.99 65.41,47.62 67.94,47.62 | 67.94,47.62 70.48,47.62 71.75,46.35 74.93,46.35 | 68.22,50.42 68.2,50.42 67.94,50.16 67.94,47.62 | 60.96,46.99 56.52,46.99 53.98,49.53 53.98,68.56 54.25,68.83
  Top 0.61: R83. 65.41,32.64 C51.
N$130
  Top 0.406: 73.97,50.42 74.3,50.75 74.3,54.61 | 74.3,54.61 74.3,55.5 | 77.78,50.42 78.11,50.75 78.11,53.98 77.47,54.61 74.3,54.61
  Top 0.61: R87. 74.3,55.5 C53.
N$131
  Top 0.61: 74.3,60.58 D75.
N$132
  Top 0.406: R88. 76.83,60.96 74.3,63.5 D76.
  Top 0.61: R88. 76.83,58.8 | 74.57,66.29 74.57,65.05 74.3,64.77 D76.
N$133
  Top 0.406: 56.19,68.83 56.52,69.16 56.52,72.39 55.5,73.41 R89.
N$134
  Top 0.406: 58.8,74.3 60.07,75.56
  Top 1.27: 60.07,75.56 LED4. | LED4. 61.59,76.83 | LED4. 61.59,73.66
  Bottom 1.27: LED4. 61.59,76.83
N$135
  Top 0.406: 66.34,50.42 66.67,50.75 66.67,54.61 | 66.67,54.61 66.67,55.5 | 70.16,50.42 70.16,50.47 70.48,50.8 70.48,53.98 69.85,54.61 66.67,54.61
  Top 0.61: R90. 66.67,55.5 C59.
N$136
  Top 0.61: 66.67,60.58 D77.
N$137
  Top 0.406: R91. 69.22,60.96 66.67,63.5 D78.
  Top 0.61: R91. 69.22,58.8 | 66.95,66.29 66.95,65.05 66.67,64.77 D78.
N$138
  Top 0.406: 58.73,50.42 58.73,50.47 59.05,50.8 59.05,54.61 | 59.05,54.61 59.05,55.5 | 62.53,50.42 62.53,50.47 62.87,50.8 62.87,53.98 62.23,54.61 59.05,54.61
  Top 0.61: R92. 59.05,55.5 C60.
N$139
  Top 0.61: 59.05,60.58 D79.
N$140
  Top 0.406: R93. 61.59,60.96 59.05,63.5 D80.
  Top 0.61: R93. 61.59,58.8 | 59.33,66.29 59.33,65.05 59.05,64.77 D80.
O_ACC  (via drill 0.61 pad 1.02)
  Top 0.406: 11.07,50.42 11.05,50.42 11.05,49.78 v10.79,49.53 | v5.71,49.53 3.81,47.62 3.81,10.79 9.53,5.08 12.06,5.08 v15.24,1.91
  Bottom 0.406: v5.71,49.53 v10.79,49.53
  Bottom 1.27: 15.24,1.27 v15.24,1.91 15.24,6.99
O_PC  (via drill 0.61 pad 1.02)
  Top 0.406: 21.23,50.42 21.21,50.42 v20.32,49.53 | v6.99,48.26 5.08,46.35 5.08,11.43 10.16,6.35 13.34,6.35 v17.78,1.91
  Bottom 0.406: v20.32,49.53 19.05,48.26 v6.99,48.26
  Bottom 1.27: 17.78,1.27 v17.78,1.91 17.78,6.99
OA_T0  (via drill 0.61 pad 1.02)
  Top 0.406: 31.39,50.42 30.73,50.42 v30.48,50.16 | v78.11,43.81 79.38,42.55 79.38,9.53 78.11,8.26 64.77,8.26 v58.42,1.91
  Top 0.813: v30.48,50.16 29.84,50.8
  Top 1.016: 29.84,50.8 29.84,52.39
  Bottom 0.406: v30.48,50.16 31.75,48.9 36.2,48.9 37.47,47.62 43.81,47.62 45.09,46.35 53.98,46.35 55.24,45.09 59.69,45.09 60.96,43.81 v78.11,43.81
  Bottom 1.27: 58.42,1.27 v58.42,1.91 58.42,6.99
OA_T1  (via drill 0.61 pad 1.02)
  Top 0.406: 56.79,50.42 56.79,49.25 v57.15,48.9 | v76.83,47.62 81.28,47.62 83.19,45.72 83.19,7.62 80.01,4.45 68.58,4.45 v66.04,1.91
  Top 0.813: v57.15,48.9 57.78,48.26
  Top 1.016: 57.78,48.26 59.05,48.26
  Bottom 0.406: v57.15,48.9 61.59,48.9 62.87,47.62 v76.83,47.62
  Bottom 1.27: 66.04,1.27 v66.04,1.91 66.04,6.99
OD_T0  (via drill 0.61 pad 1.02)
  Top 0.406: 39.01,50.42 39.01,49.17 v38.73,48.9 | v79.38,45.09 80.64,43.81 80.64,8.89 78.74,6.99 66.04,6.99 v60.96,1.91
  Bottom 0.406: v38.73,48.9 44.45,48.9 45.72,47.62 54.61,47.62 55.88,46.35 60.33,46.35 61.59,45.09 v79.38,45.09
  Bottom 1.27: 60.96,1.27 v60.96,1.91 60.96,6.99
OD_T1  (via drill 0.61 pad 1.02)
  Top 0.406: 64.41,50.42 64.41,49.17 v64.14,48.9 | v79.38,50.8 81.92,50.8 85.72,46.99 85.72,6.35 81.28,1.91 v71.12,1.91
  Bottom 0.406: v64.14,48.9 69.85,48.9 71.12,50.16 77.47,50.16 78.11,50.8 v79.38,50.8
  Bottom 1.27: 71.12,1.27 v71.12,1.91 71.12,6.99
OQ_T0  (via drill 0.61 pad 1.02)
  Top 0.406: 46.63,50.42 46.63,49.17 v46.35,48.9 | v78.11,46.35 80.64,46.35 81.92,45.09 81.92,8.26 79.38,5.71 67.31,5.71 v63.5,1.91
  Top 0.813: v46.35,48.9 45.72,48.26
  Top 1.016: 45.72,48.26 44.45,48.26
  Bottom 0.406: v46.35,48.9 55.24,48.9 56.52,47.62 60.96,47.62 62.23,46.35 v78.11,46.35
  Bottom 1.27: 63.5,1.27 v63.5,1.91 63.5,6.99
OQ_T1  (via drill 0.61 pad 1.02)
  Top 0.406: 72.03,50.42 72.03,49.17 v71.75,48.9 | v78.74,48.9 81.92,48.9 84.45,46.35 84.45,6.99 80.64,3.17 69.85,3.17 v68.58,1.91
  Top 0.813: v71.75,48.9 72.39,48.26
  Top 1.016: 72.39,48.26 73.34,48.26
  Bottom 0.406: v78.74,48.9 v71.75,48.9
  Bottom 1.27: 68.58,1.27 v68.58,1.91 68.58,6.99
Q_OUT  (via drill 0.61 pad 1.02)
  Top 0.305: 6.99,52.07 v6.99,63.5
  Top 0.406: T86. 50.16,68.35 v50.16,69.22 | T105. 75.56,68.35 v75.56,69.22 | v20.32,1.91 14.61,7.62 10.79,7.62 6.35,12.06 6.35,45.09 8.26,46.99 8.26,50.8 6.99,52.07 5.33,52.07 R103.
  Top 1.016: v75.56,69.22 73.66,69.22
  Bottom 0.305: 51.31,69.85 J3.
  Bottom 0.406: v6.99,63.5 11.43,67.94 26.04,67.94 27.3,69.22 v50.16,69.22 50.8,69.22 51.31,69.72 51.31,69.85 | J3. 53.34,69.22 v75.56,69.22
  Bottom 1.27: 20.32,1.27 v20.32,1.91 20.32,6.99
VCC  (via drill 0.61 pad 1.02)
  Top 0.61: 26.67,19.43 v26.67,20.32 C16. | 34.29,19.43 v34.29,20.32 C17. | 17.14,19.43 v17.14,20.32 C8. | 9.53,19.43 v9.53,20.32 C7. | 43.81,19.43 v43.81,20.32 C42. | 51.44,19.43 v51.44,20.32 C43. | 60.96,19.43 v60.96,20.32 C54. | 68.58,19.43 v68.58,20.32 C55. | C56. v62.87,36.83 62.87,35.94 | C57. v71.75,36.83 71.75,35.94 | C44. v45.09,36.83 45.09,35.94 | C45. v53.98,36.83 53.98,35.94 | C19. v36.2,36.83 36.2,35.94 | C18. v27.3,36.83 27.3,35.94 | C9. v9.53,36.83 9.53,35.94 | C10. v18.41,36.83 18.41,35.94 | C11. v10.79,59.69 10.79,58.8 | C20. v20.95,59.69 20.95,58.8 | 31.11,58.8 v31.11,59.69 C46. | C67. v38.73,59.69 38.73,58.8 | C68. v46.35,59.69 46.35,58.8 | 56.52,58.8 v56.52,59.69 C58. | C66. v71.75,59.69 71.75,58.8 | 64.14,58.8 v64.14,59.69 C65. | v77.47,20.32 77.47,21.21 | v60.96,29.21 61.98,29.21 | v43.81,29.21 44.83,29.21 | v26.67,29.21 27.69,29.21 | v5.08,57.15 5.08,55.63 | 64.14,71.5 v64.14,73.66 70.23,73.66 71.12,72.77
  Top 1.27: 20.95,76.83 20.95,75.56 20.95,73.66 | 32.38,76.83 32.38,75.56 32.38,73.66 | 47.62,76.83 47.62,75.56 47.62,73.66 | 64.14,76.83 64.14,75.56 v64.14,73.66
  Bottom 0.61: v68.58,20.32 v77.47,20.32 | 26.67,36.83 v26.67,29.21 | 43.81,36.83 v43.81,29.21 | 60.96,36.83 v60.96,29.21 | 2.54,57.15 v5.08,57.15
  Bottom 1.27: v68.58,20.32 v60.96,20.32 v51.44,20.32 v43.81,20.32 v34.29,20.32 v26.67,20.32 v17.14,20.32 v9.53,20.32 2.54,20.32 | v71.75,59.69 v64.14,59.69 v56.52,59.69 v46.35,59.69 v38.73,59.69 v31.11,59.69 v20.95,59.69 v10.79,59.69 2.54,59.69 | v71.75,36.83 v62.87,36.83 60.96,36.83 v53.98,36.83 v45.09,36.83 43.81,36.83 v36.2,36.83 v27.3,36.83 26.67,36.83 v18.41,36.83 v9.53,36.83 2.54,36.83 | 2.54,36.83 2.54,57.15 2.54,59.69 | 2.54,20.32 2.54,36.83 | 2.54,1.27 2.54,5.71 | 2.54,5.71 2.54,6.99 | 2.54,6.99 2.54,20.32 | 47.62,73.66 50.16,76.2 57.78,76.2 60.33,73.66 v64.14,73.66 64.14,75.56 64.14,76.83 | 32.38,73.66 47.62,73.66 | 20.95,73.66 32.38,73.66 | 20.95,73.66 10.16,73.66 2.54,66.04 2.54,59.69 | 20.95,73.66 20.95,75.56 20.95,76.83 | 32.38,73.66 32.38,75.56 32.38,76.83 | 47.62,73.66 47.62,75.56 47.62,76.83 | 5.08,6.99 5.08,1.27 | 2.54,6.99 5.08,6.99 | 7.62,5.71 7.62,6.99 5.08,6.99 | 7.62,5.71 7.62,1.27 | 2.54,5.71 7.62,5.71
  pour Bottom (isolate 0.356): 8.26,3.81 1.27,3.81 1.27,60.96 73.03,60.96 73.03,57.15 6.99,57.15 6.99,50.8 4.45,50.8 4.45,48.9 6.99,46.35 6.99,38.1 73.03,38.1 73.03,33.66 6.99,33.66 6.99,21.59 76.83,21.59 78.11,20.32 75.56,17.78 6.99,17.78 6.99,13.97 8.26,12.7

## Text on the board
tNames: A | D | Q | A | Q | D | ACC | PC | T0 | T1 | VCC | VCC | VCC | ALU_PC | ALU_A | O_ACC | O_PC | Q_OUT | L_ACC | I_A | I_PC | L_PC | GND | GND | L_T0 | ALU_Q0 | ALU_Q1 | L_T1 | OA_T0 | OD_T0 | OQ_T0 | OA_T1 | OQ_T1 | OD_T1 | GND | GND | GND | A | D_OUT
